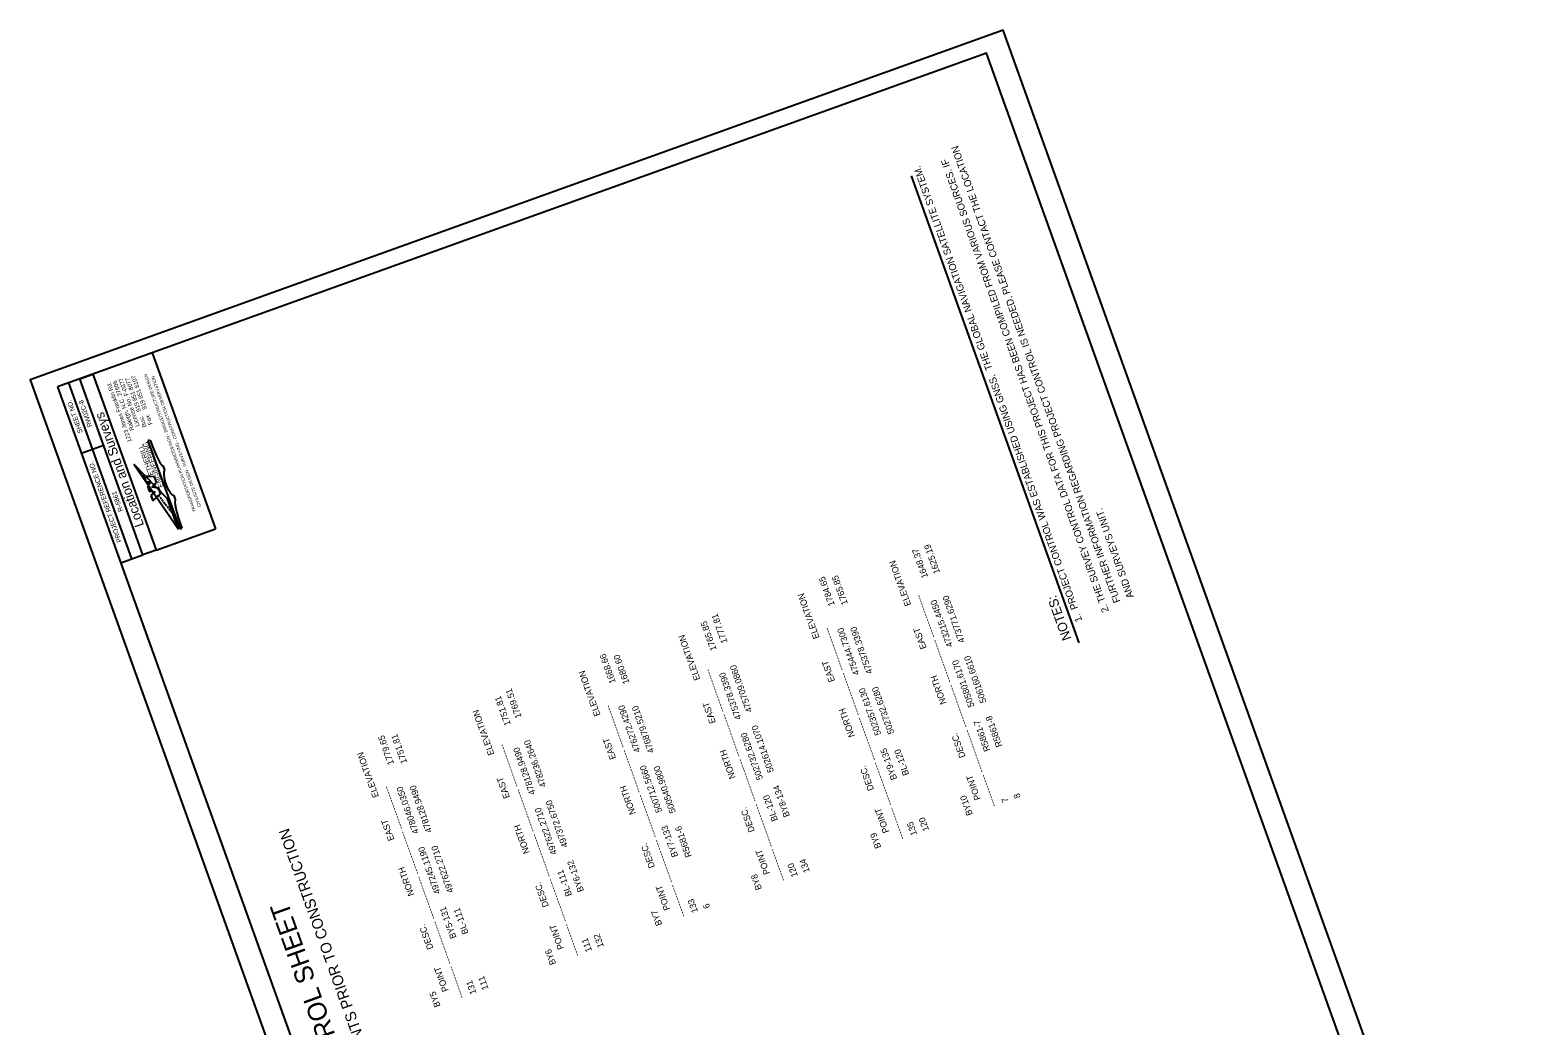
# Model space of a CAD drawing. Extents: x 473103 to 476656, y 504228 to 508561.
# Drawn here: x 473103 to 476656, y 506216 to 508561 of the extents above; entities that cross this region are included whole.
import ezdxf

# ---------------------------------------------------------------- set-up
doc = ezdxf.new("R2010")
doc.units = 0
for name, color, linetype in [('CTL Sheet Border CELL', 7, 'Continuous'), ('CTL Sheet Notes CELL', 7, 'Continuous'), ('CTL Sheet Text', 7, 'Continuous'), ('Sheet Plot Border Outside CELL', 7, 'Continuous')]:
    doc.layers.add(name, color=color, linetype=linetype)

msp = doc.modelspace()

# ---------------------------------------------------------------- linework, layer by layer
at = {"layer": 'CTL Sheet Border CELL'}
for p, q in [((473540.4, 507386.5), (473391.5, 507801.1)), ((473153.3, 507745), (473153.3, 507745)), ((473153.3, 507745), (473153.3, 507745)), ((473103.2, 507737.6), (473103.2, 507737.6)), ((473343, 507315.7), (473194.2, 507730.3)), ((473224.2, 507564.6), (473276.3, 507583.3)), ((473399.8, 507336), (473540.3, 507386.5)), ((473317, 507306.3), (473369.1, 507325))]:
    msp.add_line(p, q, dxfattribs=at)
for points in [[(473168, 507720.9), (474290.6, 504594.3), (476479.2, 505380.1), (475356.6, 508506.7)], [(473369.1, 507325), (473220.2, 507739.6), (473250.9, 507750.6), (473399.8, 507336)]]:
    msp.add_lwpolyline(points, close=True, dxfattribs=at)
at = {"layer": 'CTL Sheet Notes CELL'}
for p, q in [((475575.1, 507118.1), (475180.3, 508217.5)), ((473385.6, 507594.9), (473380.9, 507593.2)), ((473380.9, 507593.2), (473455.9, 507386.3)), ((473420.9, 507524.4), (473417.5, 507533.8)), ((473367.4, 507513.9), (473364.4, 507517.8)), ((473371.5, 507508.6), (473368.5, 507512.6)), ((473371.3, 507510.3), (473375.8, 507497.8)), ((473396.2, 507508.5), (473371.8, 507509.9)), ((473371.8, 507509.9), (473376, 507498.1)), ((473375.8, 507497.8), (473388.6, 507497.1)), ((473376, 507498.1), (473389.3, 507497.4)), ((473388.6, 507497.1), (473379.6, 507487.2)), ((473389.3, 507497.4), (473380, 507487.2)), ((473383.8, 507492.9), (473380.8, 507496.8)), ((473390, 507484.1), (473400.7, 507496)), ((473390.6, 507484.4), (473401.1, 507495.9)), ((473400.7, 507496), (473396.2, 507508.5)), ((473401.1, 507495.9), (473396.4, 507508.9)), ((473379.6, 507487.2), (473384, 507475.1)), ((473380, 507487.2), (473384.3, 507475.4)), ((473384, 507475.1), (473397.2, 507473.3)), ((473384.3, 507475.4), (473398, 507473.5)), ((473397.2, 507473.3), (473387.9, 507464.5)), ((473387.9, 507464.5), (473392.4, 507452.1)), ((473398, 507473.5), (473388.2, 507464.4)), ((473388.2, 507464.4), (473392.5, 507452.7)), ((473405.9, 507481.9), (473390, 507484.1)), ((473406.1, 507482.2), (473390.6, 507484.4)), ((473392.4, 507452.1), (473410.8, 507469.3)), ((473392.5, 507452.7), (473410.4, 507469.4)), ((473408.4, 507461.3), (473405.3, 507465.3)), ((473410.4, 507469.4), (473405.9, 507481.9)), ((473410.8, 507469.3), (473406.1, 507482.2)), ((473412.5, 507456.1), (473409.4, 507460)), ((473445.9, 507455.4), (473442.5, 507464.8)), ((473416.6, 507450.8), (473413.5, 507454.7)), ((473420.7, 507445.5), (473417.6, 507449.5)), ((473424.8, 507440.3), (473421.7, 507444.2)), ((473428.9, 507435), (473425.8, 507439)), ((473433, 507429.8), (473429.9, 507433.7)), ((473437.1, 507424.5), (473434, 507428.5)), ((473455.9, 507386.3), (473460.6, 507388))]:
    msp.add_line(p, q, dxfattribs=at)
msp.add_lwpolyline([(473452.7, 507385.2), (473426.6, 507457.3), (473348.5, 507538.2)], close=True, dxfattribs=at)
msp.add_lwpolyline([(473396.4, 507508.9), (473396, 507508.9), (473371.3, 507510.3)], dxfattribs=at)
for centre, major_axis, ratio, start_param, end_param in [((473394.3, 507598), (-23.3, 64.2), 0.134146, 1.570796, 3.141593), ((473431.7, 507494.6), (-10.8, 29.8), 0.289474, 0, 3.141593), ((473469.2, 507391.2), (23.3, -64.2), 0.134146, 3.141593, 4.712389)]:
    msp.add_ellipse(centre, major_axis=major_axis, ratio=ratio, start_param=start_param, end_param=end_param, dxfattribs=at)
at = {"layer": 'Sheet Plot Border Outside CELL'}
msp.add_lwpolyline([(476656.3, 505050.7), (475396, 508560.9), (473103.2, 507737.6), (474363.5, 504227.5)], close=True, dxfattribs=at)

# ---------------------------------------------------------------- texts
at = {"layer": 'CTL Sheet Border CELL'}
for s, height, p in [('SHEET NO.', 11.07, (473227.3, 507613.5)), ('RW02C-8', 11.07, (473249.9, 507628)), ('Location and Surveys', 22.147, (473371.8, 507395)), ('PROJECT REFERENCE NO.', 11.074, (473319.2, 507356.7)), ('R-5861', 11.07, (473322.4, 507429.1)), ('W/  EXISTING CENTERLINE ALIGNMENTS PRIOR TO CONSTRUCTION', 25.469, (474095.3, 505616.4)), ('SURVEY CONTROL SHEET ', 44.294, (473967.3, 505792.2))]:
    msp.add_text(s, height=height, rotation=109.7508, dxfattribs=at).set_placement(p)
at = {"layer": 'CTL Sheet Notes CELL'}
for s, height, rotation, p in [('  FURTHER INFORMATION REGARDING PROJECT CONTROL IS NEEDED, PLEASE CONTACT THE LOCATION', 16.606, 109.6455, (475677, 507203.7)), ('1.  PROJECT CONTROL WAS ESTABLISHED USING GNSS,  THE GLOBAL NAVIGATION SATELLITE SYSTEM.', 16.606, 109.6455, (475583.1, 507170.2)), ('2. THE SURVEY CONTROL DATA FOR THIS PROJECT HAS BEEN COMPILED FROM VARIOUS SOURCES. IF', 16.606, 109.6455, (475645.7, 507192.5)), ('Fax:   919 851 8107', 10, 109.7508, (473391.7, 507633.1)), ('1223 Jones Franklin Rd. ', 10, 109.7508, (473342.7, 507592.2)), ('Raleigh, N.C. 27606', 10, 109.7508, (473348.7, 507619.7)), ('License No. F-0377', 10, 109.7508, (473361.3, 507628.9)), ('Bus:   919 851 8077', 10, 109.7508, (473377.9, 507627.3)), ('TRANSPORTATION PLANNING/DESIGN - BRIDGE/STRUCTURE DESIGN', 7.333, 109.7508, (473494.4, 507427.8)), ('CIVIL/SITE DESIGN - SURVEYING - CONSTRUCTION OBSERVATION', 7.333, 109.7508, (473506.1, 507438.7)), ('ETHERILL', 11.67, 109.9099, (473394.3, 507513.8)), ('ENGINEERING', 11.667, 109.9099, (473417.9, 507486.2)), ('  AND SURVEYS UNIT. ', 16.606, 109.6455, (475708.3, 507214.9)), ('NOTES:', 22.15, 109.6455, (475557.5, 507127.9))]:
    msp.add_text(s, height=height, rotation=rotation, dxfattribs=at).set_placement(p)
at = {"layer": 'CTL Sheet Text'}
for s, p in [('7                     R5861-7      505801.6170      473215.4450          1648.37', (475409.5, 506744.3)), ('8                     R5861-8      506160.6610      473771.6290          1625.19', (475437.8, 506754.5)), ('     POINT        DESC.             NORTH            EAST          ELEVATION', (475353.1, 506724)), ('135                   BY9-135      502357.6130      475444.7300          1784.65', (475193.8, 506666.8)), ('120                   BL-120       502732.6280      475378.3390          1765.85', (475222, 506677)), ('     POINT        DESC.             NORTH            EAST          ELEVATION', (475137.3, 506646.6)), ('------------ ---------------- ---------------- ---------------- ----------------', (475381.3, 506734.2)), ('134                   BY8-134      502614.1070      475709.0860          1777.81', (474941, 506579.2)), ('120                   BL-120       502732.6280      475378.3390          1765.85', (474912.7, 506569.1)), ('------------ ---------------- ---------------- ---------------- ----------------', (475165.6, 506656.7)), ('     POINT        DESC.             NORTH            EAST          ELEVATION', (474856.3, 506548.8)), ('133                   BY7-133      500712.5660      476272.4290          1668.66', (474677.6, 506484.7)), ('6                     R5681-6      500540.9800      476879.5210          1680.60', (474705.8, 506494.8)), ('     POINT        DESC.             NORTH            EAST          ELEVATION', (474621.1, 506464.4)), ('------------ ---------------- ---------------- ---------------- ----------------', (474884.5, 506559)), ('132                   BY6-132      497372.6750      478236.2640          1769.51', (474455.7, 506402.7)), ('     POINT        DESC.             NORTH            EAST          ELEVATION', (474371, 506372.3)), ('111                   BL-111       497622.2710      478128.9490          1751.81', (474427.5, 506392.6)), ('------------ ---------------- ---------------- ---------------- ----------------', (474649.3, 506474.6)), ('131                   BY5-131      497245.1190      478046.0350          1779.65', (474155.3, 506292.9)), ('111                   BL-111       497622.2710      478128.9490          1751.81', (474183.6, 506303.1)), ('     POINT        DESC.             NORTH            EAST          ELEVATION', (474098.9, 506272.7)), ('------------ ---------------- ---------------- ---------------- ----------------', (474399.3, 506382.4)), ('------------ ---------------- ---------------- ---------------- ----------------', (474127.1, 506282.8)), ('BY10', (475324.8, 506713.9)), ('BY9', (475109.1, 506636.4)), ('BY8', (474828, 506538.7)), ('BY7', (474592.9, 506454.3)), ('BY6', (474342.8, 506362.2)), ('BY5', (474070.6, 506262.5))]:
    msp.add_text(s, height=15, rotation=109.7508, dxfattribs=at).set_placement(p)

doc.saveas('drawing.dxf')
